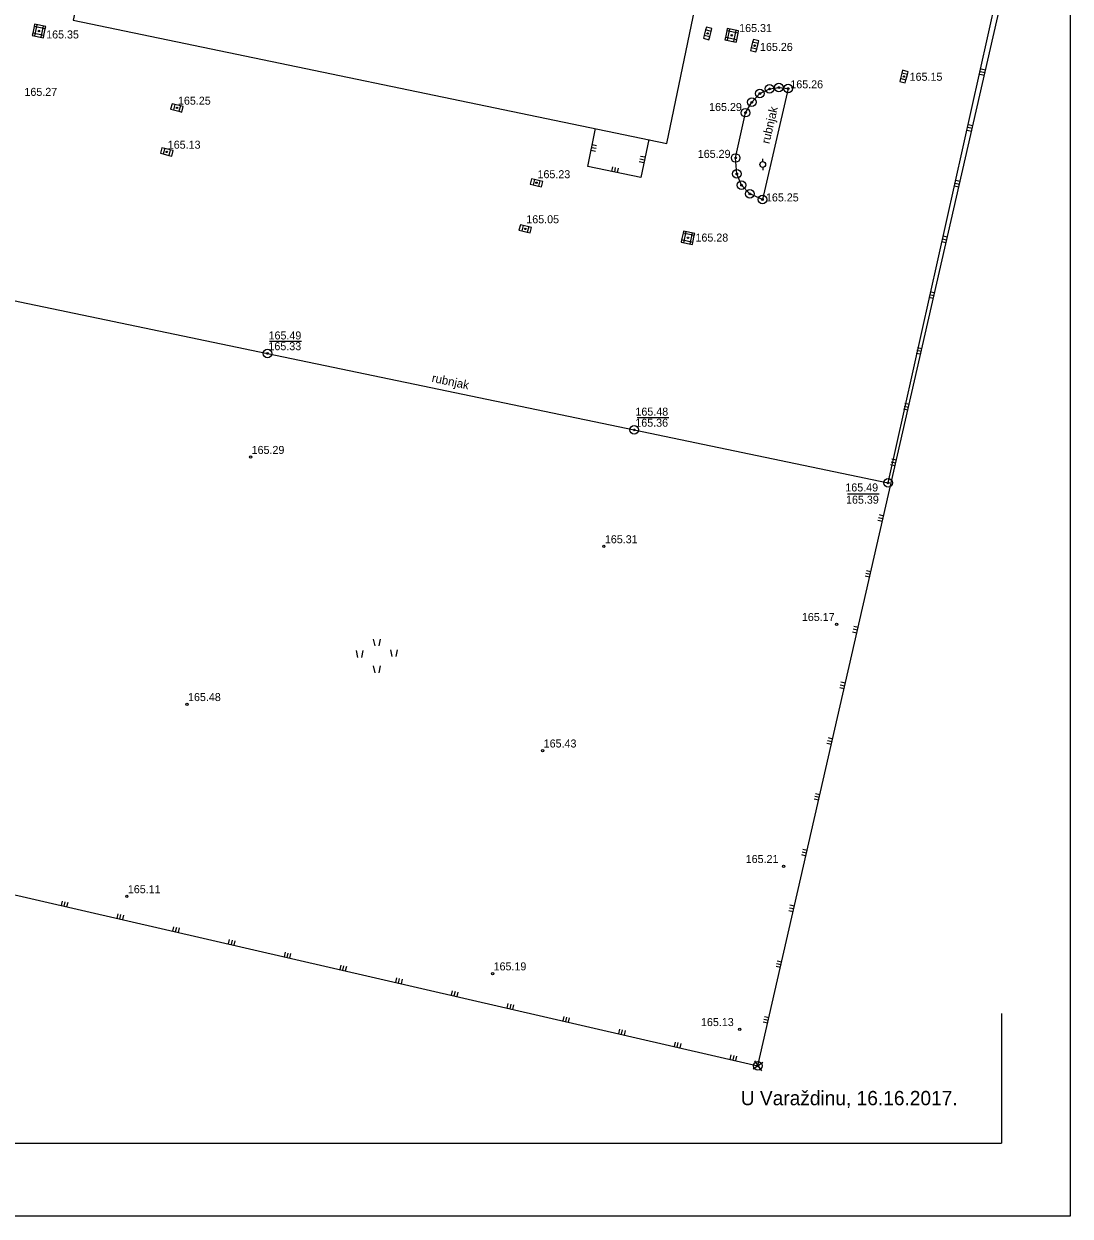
# Model space of a CAD drawing. Extents: x 492698 to 492905, y 5129124 to 5129334.
# Drawn here: x 492805.9 to 492897.4, y 5129123.7 to 5129228 of the extents above; entities that cross this region are included whole.
import ezdxf

# ---------------------------------------------------------------- set-up
doc = ezdxf.new("R2010")
doc.units = 0
for name, color, linetype in [('KUĆNI BROJ', 7, 'Continuous'), ('MEĐA - stara', 7, 'Continuous'), ('MEĐAŠI', 7, 'Continuous'), ('OBJEKTI - novi', 7, 'Continuous'), ('OBJEKTI - stari', 7, 'Continuous'), ('OBRAZCI', 7, 'Continuous'), ('TOPO - Znakovi', 7, 'Continuous'), ('VISINE', 7, 'Continuous')]:
    doc.layers.add(name, color=color, linetype=linetype)

msp = doc.modelspace()

# ---------------------------------------------------------------- linework, layer by layer
at = {"layer": 'MEĐA - stara'}
for p, q in [((492870.12, 5129136.86), (492891.58, 5129230.79)), ((492881.5, 5129187.83), (492890.99, 5129230.4)), ((492870.29, 5129221.87), (492871.14, 5129222.28)), ((492872.77, 5129222.31), (492870.51, 5129212.6)), ((492871.14, 5129222.28), (492871.94, 5129222.4)), ((492871.94, 5129222.4), (492872.77, 5129222.31)), ((492869.58, 5129221.11), (492870.29, 5129221.87)), ((492868.17, 5129216.24), (492869.04, 5129220.2)), ((492869.04, 5129220.2), (492869.58, 5129221.11)), ((492868.27, 5129214.85), (492868.17, 5129216.24)), ((492868.69, 5129213.86), (492868.27, 5129214.85)), ((492869.42, 5129213.1), (492868.69, 5129213.86)), ((492870.51, 5129212.6), (492869.42, 5129213.1)), ((492792.93, 5129206.3), (492827.24, 5129199.15)), ((492827.24, 5129199.15), (492859.31, 5129192.46)), ((492859.31, 5129192.46), (492881.5, 5129187.83)), ((492834.99, 5129173.17), (492835.12, 5129172.57)), ((492835.59, 5129173.17), (492835.47, 5129172.57)), ((492836.49, 5129174.17), (492836.62, 5129173.57)), ((492837.09, 5129174.17), (492836.97, 5129173.57)), ((492837.99, 5129173.24), (492838.12, 5129172.64)), ((492838.59, 5129173.24), (492838.47, 5129172.64)), ((492836.49, 5129171.82), (492836.62, 5129171.22)), ((492837.09, 5129171.82), (492836.97, 5129171.22)), ((492788.55, 5129155.62), (492870.12, 5129136.86))]:
    msp.add_line(p, q, dxfattribs=at)
at = {"layer": 'MEĐAŠI'}
for p, q in [((492870.55, 5129137.16), (492869.69, 5129136.56)), ((492869.82, 5129137.29), (492870.42, 5129136.43))]:
    msp.add_line(p, q, dxfattribs=at)
for centre, radius in [((492870.29, 5129221.87), 0.375), ((492871.14, 5129222.28), 0.375), ((492871.14, 5129222.28), 0.075), ((492871.94, 5129222.4), 0.375), ((492871.94, 5129222.4), 0.075), ((492872.77, 5129222.31), 0.375), ((492872.77, 5129222.31), 0.075), ((492869.58, 5129221.11), 0.375), ((492869.58, 5129221.11), 0.075), ((492870.29, 5129221.87), 0.075), ((492869.04, 5129220.2), 0.375), ((492869.04, 5129220.2), 0.075), ((492868.17, 5129216.24), 0.375), ((492868.17, 5129216.24), 0.075), ((492868.27, 5129214.85), 0.375), ((492868.27, 5129214.85), 0.075), ((492868.69, 5129213.86), 0.375), ((492868.69, 5129213.86), 0.075), ((492869.42, 5129213.1), 0.375), ((492869.42, 5129213.1), 0.075), ((492870.51, 5129212.6), 0.375), ((492870.51, 5129212.6), 0.075), ((492827.24, 5129199.15), 0.375), ((492827.24, 5129199.15), 0.075), ((492859.31, 5129192.46), 0.375), ((492859.31, 5129192.46), 0.075), ((492881.5, 5129187.83), 0.375), ((492881.5, 5129187.83), 0.075), ((492870.12, 5129136.86), 0.075)]:
    msp.add_circle(centre, radius, dxfattribs=at)
for start, end in [(170.0551, 350.0551), (350.0551, 170.0551)]:
    msp.add_arc((492870.12, 5129136.86), 0.075, start, end, dxfattribs=at)
at = {"layer": 'OBJEKTI - novi'}
msp.add_circle((492870.12, 5129136.86), 0.375, dxfattribs=at)
at = {"layer": 'OBJEKTI - stari'}
for p, q in [((492855.25, 5129215.5), (492855.91, 5129218.81)), ((492860.57, 5129217.85), (492859.87, 5129214.53)), ((492859.87, 5129214.53), (492855.25, 5129215.5))]:
    msp.add_line(p, q, dxfattribs=at)
msp.add_lwpolyline([(492818.96, 5129270.18), (492815.01, 5129251.01), (492812.14, 5129237.15), (492810.27, 5129228.29), (492862.15, 5129217.52), (492870.87, 5129259.44)], close=True, dxfattribs=at)
at = {"layer": 'OBRAZCI'}
for p, q in [((492897.41, 5129333.71), (492897.41, 5129123.71)), ((492891.41, 5129141.43), (492891.41, 5129130.09)), ((492754.91, 5129130.09), (492891.41, 5129130.09)), ((492897.41, 5129123.71), (492748.91, 5129123.71))]:
    msp.add_line(p, q, dxfattribs=at)
at = {"layer": 'TOPO - Znakovi'}
for p, q in [((492806.84, 5129227.74), (492806.72, 5129227.15)), ((492806.88, 5129227.93), (492806.84, 5129227.74)), ((492807.82, 5129227.53), (492806.84, 5129227.74)), ((492807.08, 5129227.89), (492806.87, 5129226.91)), ((492807.86, 5129227.73), (492806.88, 5129227.93)), ((492807.46, 5129226.79), (492807.67, 5129227.77)), ((492807.7, 5129226.94), (492807.82, 5129227.53)), ((492807.82, 5129227.53), (492807.86, 5129227.73)), ((492865.55, 5129227.44), (492865.42, 5129226.95)), ((492865.62, 5129227.68), (492865.55, 5129227.44)), ((492866.04, 5129227.31), (492865.55, 5129227.44)), ((492866.1, 5129227.55), (492865.62, 5129227.68)), ((492866.04, 5129227.31), (492866.1, 5129227.55)), ((492867.44, 5129227.56), (492867.4, 5129227.37)), ((492867.64, 5129227.52), (492867.43, 5129226.54)), ((492868.42, 5129227.36), (492867.44, 5129227.56)), ((492868.02, 5129226.42), (492868.23, 5129227.4)), ((492806.72, 5129227.15), (492806.68, 5129226.95)), ((492806.68, 5129226.95), (492807.66, 5129226.75)), ((492807.7, 5129226.94), (492806.72, 5129227.15)), ((492807.66, 5129226.75), (492807.7, 5129226.94)), ((492865.42, 5129226.95), (492865.36, 5129226.71)), ((492865.36, 5129226.71), (492865.84, 5129226.58)), ((492865.91, 5129226.82), (492865.42, 5129226.95)), ((492865.84, 5129226.58), (492865.91, 5129226.82)), ((492865.91, 5129226.82), (492866.04, 5129227.31)), ((492867.28, 5129226.78), (492867.24, 5129226.58)), ((492867.24, 5129226.58), (492868.22, 5129226.38)), ((492867.4, 5129227.37), (492867.28, 5129226.78)), ((492868.26, 5129226.57), (492867.28, 5129226.78)), ((492868.38, 5129227.16), (492867.4, 5129227.37)), ((492868.22, 5129226.38), (492868.26, 5129226.57)), ((492868.26, 5129226.57), (492868.38, 5129227.16)), ((492868.38, 5129227.16), (492868.42, 5129227.36)), ((492869.65, 5129226.37), (492869.52, 5129225.88)), ((492869.72, 5129226.61), (492869.65, 5129226.37)), ((492870.14, 5129226.24), (492869.65, 5129226.37)), ((492870.2, 5129226.48), (492869.72, 5129226.61)), ((492870.14, 5129226.24), (492870.2, 5129226.48)), ((492869.52, 5129225.88), (492869.46, 5129225.64)), ((492869.46, 5129225.64), (492869.94, 5129225.51)), ((492870.01, 5129225.75), (492869.52, 5129225.88)), ((492869.94, 5129225.51), (492870.01, 5129225.75)), ((492870.01, 5129225.75), (492870.14, 5129226.24)), ((492882.7, 5129223.67), (492882.57, 5129223.18)), ((492882.77, 5129223.91), (492882.7, 5129223.67)), ((492883.19, 5129223.54), (492882.7, 5129223.67)), ((492883.25, 5129223.78), (492882.77, 5129223.91)), ((492883.06, 5129223.05), (492883.19, 5129223.54)), ((492883.19, 5129223.54), (492883.25, 5129223.78)), ((492889.52, 5129223.56), (492889.91, 5129223.47)), ((492889.57, 5129223.8), (492889.96, 5129223.71)), ((492889.63, 5129224.04), (492890.02, 5129223.96)), ((492882.57, 5129223.18), (492882.51, 5129222.94)), ((492882.51, 5129222.94), (492882.99, 5129222.81)), ((492883.06, 5129223.05), (492882.57, 5129223.18)), ((492882.99, 5129222.81), (492883.06, 5129223.05)), ((492818.9, 5129220.98), (492818.78, 5129220.5)), ((492818.78, 5129220.5), (492819.03, 5129220.44)), ((492819.15, 5129220.92), (492818.9, 5129220.98)), ((492819.15, 5129220.92), (492819.03, 5129220.44)), ((492819.03, 5129220.44), (492819.51, 5129220.32)), ((492819.63, 5129220.8), (492819.15, 5129220.92)), ((492819.63, 5129220.8), (492819.51, 5129220.32)), ((492819.51, 5129220.32), (492819.76, 5129220.26)), ((492819.88, 5129220.74), (492819.63, 5129220.8)), ((492819.76, 5129220.26), (492819.88, 5129220.74)), ((492888.51, 5129219.17), (492888.9, 5129219.08)), ((492888.4, 5129218.68), (492888.79, 5129218.59)), ((492888.46, 5129218.93), (492888.85, 5129218.84)), ((492818.01, 5129217.13), (492817.89, 5129216.65)), ((492818.26, 5129217.07), (492818.01, 5129217.13)), ((492818.26, 5129217.07), (492818.14, 5129216.59)), ((492818.74, 5129216.95), (492818.26, 5129217.07)), ((492818.74, 5129216.95), (492818.62, 5129216.47)), ((492818.99, 5129216.89), (492818.74, 5129216.95)), ((492855.97, 5129217.06), (492855.58, 5129217.14)), ((492856.02, 5129217.31), (492855.63, 5129217.39)), ((492817.89, 5129216.65), (492818.14, 5129216.59)), ((492818.14, 5129216.59), (492818.62, 5129216.47)), ((492818.62, 5129216.47), (492818.87, 5129216.41)), ((492818.87, 5129216.41), (492818.99, 5129216.89)), ((492855.92, 5129216.82), (492855.53, 5129216.9)), ((492859.75, 5129215.92), (492860.14, 5129215.84)), ((492859.8, 5129216.16), (492860.2, 5129216.08)), ((492859.86, 5129216.41), (492860.25, 5129216.33)), ((492870.54, 5129215.92), (492870.54, 5129216.17)), ((492857.4, 5129215.46), (492857.32, 5129215.07)), ((492857.65, 5129215.41), (492857.57, 5129215.01)), ((492857.89, 5129215.35), (492857.81, 5129214.96)), ((492870.54, 5129215.42), (492870.54, 5129215.17)), ((492850.33, 5129214.43), (492850.21, 5129213.95)), ((492850.21, 5129213.95), (492850.46, 5129213.89)), ((492850.58, 5129214.37), (492850.33, 5129214.43)), ((492850.58, 5129214.37), (492850.46, 5129213.89)), ((492850.46, 5129213.89), (492850.94, 5129213.77)), ((492851.06, 5129214.25), (492850.58, 5129214.37)), ((492851.06, 5129214.25), (492850.94, 5129213.77)), ((492851.31, 5129214.19), (492851.06, 5129214.25)), ((492851.19, 5129213.71), (492851.31, 5129214.19)), ((492887.35, 5129214.05), (492887.74, 5129213.96)), ((492887.4, 5129214.3), (492887.79, 5129214.21)), ((492850.94, 5129213.77), (492851.19, 5129213.71)), ((492887.29, 5129213.81), (492887.68, 5129213.72)), ((492849.35, 5129210.4), (492849.23, 5129209.92)), ((492849.23, 5129209.92), (492849.48, 5129209.86)), ((492849.6, 5129210.34), (492849.35, 5129210.4)), ((492849.6, 5129210.34), (492849.48, 5129209.86)), ((492849.48, 5129209.86), (492849.96, 5129209.74)), ((492850.08, 5129210.22), (492849.6, 5129210.34)), ((492850.08, 5129210.22), (492849.96, 5129209.74)), ((492849.96, 5129209.74), (492850.21, 5129209.68)), ((492850.33, 5129210.16), (492850.08, 5129210.22)), ((492850.21, 5129209.68), (492850.33, 5129210.16)), ((492863.57, 5129209.66), (492863.45, 5129209.07)), ((492863.61, 5129209.85), (492863.57, 5129209.66)), ((492864.55, 5129209.45), (492863.57, 5129209.66)), ((492863.81, 5129209.81), (492863.6, 5129208.83)), ((492864.59, 5129209.65), (492863.61, 5129209.85)), ((492864.19, 5129208.71), (492864.4, 5129209.69)), ((492864.55, 5129209.45), (492864.59, 5129209.65)), ((492863.45, 5129209.07), (492863.41, 5129208.87)), ((492863.41, 5129208.87), (492864.39, 5129208.67)), ((492864.43, 5129208.86), (492863.45, 5129209.07)), ((492864.39, 5129208.67), (492864.43, 5129208.86)), ((492864.43, 5129208.86), (492864.55, 5129209.45)), ((492886.18, 5129208.93), (492886.57, 5129208.84)), ((492886.23, 5129209.18), (492886.62, 5129209.09)), ((492886.29, 5129209.42), (492886.68, 5129209.33)), ((492885.17, 5129204.55), (492885.56, 5129204.46)), ((492885.06, 5129204.06), (492885.45, 5129203.97)), ((492885.12, 5129204.3), (492885.51, 5129204.21)), ((492884, 5129199.43), (492884.39, 5129199.34)), ((492884.06, 5129199.67), (492884.45, 5129199.58)), ((492883.95, 5129199.18), (492884.34, 5129199.1)), ((492882.84, 5129194.31), (492883.23, 5129194.22)), ((492882.89, 5129194.55), (492883.28, 5129194.46)), ((492882.95, 5129194.8), (492883.34, 5129194.71)), ((492881.83, 5129189.92), (492882.22, 5129189.83)), ((492881.72, 5129189.44), (492882.11, 5129189.35)), ((492881.78, 5129189.68), (492882.17, 5129189.59)), ((492880.66, 5129184.81), (492881.05, 5129184.72)), ((492880.72, 5129185.05), (492881.11, 5129184.96)), ((492880.61, 5129184.56), (492881, 5129184.47)), ((492879.49, 5129179.69), (492879.88, 5129179.6)), ((492879.55, 5129179.93), (492879.94, 5129179.84)), ((492879.61, 5129180.17), (492880, 5129180.09)), ((492878.49, 5129175.3), (492878.88, 5129175.21)), ((492878.38, 5129174.81), (492878.77, 5129174.72)), ((492878.44, 5129175.06), (492878.83, 5129174.97)), ((492877.32, 5129170.18), (492877.71, 5129170.09)), ((492877.38, 5129170.43), (492877.77, 5129170.34)), ((492877.27, 5129169.94), (492877.66, 5129169.85)), ((492876.15, 5129165.06), (492876.54, 5129164.97)), ((492876.21, 5129165.31), (492876.6, 5129165.22)), ((492876.26, 5129165.55), (492876.65, 5129165.46)), ((492875.15, 5129160.68), (492875.54, 5129160.59)), ((492875.04, 5129160.19), (492875.43, 5129160.1)), ((492875.1, 5129160.43), (492875.49, 5129160.34)), ((492873.98, 5129155.56), (492874.37, 5129155.47)), ((492874.04, 5129155.8), (492874.43, 5129155.71)), ((492873.93, 5129155.32), (492874.32, 5129155.23)), ((492809.29, 5129151.26), (492809.2, 5129150.87)), ((492809.53, 5129151.2), (492809.44, 5129150.81)), ((492809.78, 5129151.15), (492809.69, 5129150.76)), ((492872.81, 5129150.44), (492873.2, 5129150.35)), ((492872.87, 5129150.68), (492873.26, 5129150.6)), ((492872.92, 5129150.93), (492873.31, 5129150.84)), ((492814.16, 5129150.14), (492814.07, 5129149.75)), ((492814.41, 5129150.08), (492814.32, 5129149.69)), ((492814.65, 5129150.03), (492814.56, 5129149.64)), ((492819.04, 5129149.02), (492818.95, 5129148.63)), ((492819.28, 5129148.96), (492819.19, 5129148.57)), ((492819.52, 5129148.91), (492819.43, 5129148.52)), ((492823.91, 5129147.9), (492823.82, 5129147.51)), ((492824.15, 5129147.84), (492824.06, 5129147.45)), ((492824.4, 5129147.79), (492824.31, 5129147.4)), ((492828.78, 5129146.78), (492828.69, 5129146.39)), ((492829.02, 5129146.72), (492828.94, 5129146.33)), ((492829.27, 5129146.67), (492829.18, 5129146.28)), ((492871.81, 5129146.05), (492872.2, 5129145.96)), ((492833.65, 5129145.66), (492833.56, 5129145.27)), ((492833.9, 5129145.6), (492833.81, 5129145.21)), ((492834.14, 5129145.55), (492834.05, 5129145.16)), ((492871.7, 5129145.57), (492872.09, 5129145.48)), ((492871.75, 5129145.81), (492872.14, 5129145.72)), ((492838.53, 5129144.54), (492838.44, 5129144.15)), ((492838.77, 5129144.48), (492838.68, 5129144.09)), ((492839.01, 5129144.42), (492838.92, 5129144.03)), ((492843.4, 5129143.42), (492843.31, 5129143.03)), ((492843.64, 5129143.36), (492843.55, 5129142.97)), ((492843.89, 5129143.3), (492843.8, 5129142.91)), ((492848.27, 5129142.3), (492848.18, 5129141.91)), ((492848.52, 5129142.24), (492848.43, 5129141.85)), ((492848.76, 5129142.18), (492848.67, 5129141.79)), ((492853.15, 5129141.17), (492853.06, 5129140.78)), ((492853.39, 5129141.12), (492853.3, 5129140.73)), ((492853.63, 5129141.06), (492853.54, 5129140.67)), ((492870.64, 5129140.94), (492871.03, 5129140.85)), ((492870.7, 5129141.18), (492871.09, 5129141.09)), ((492858.02, 5129140.05), (492857.93, 5129139.66)), ((492858.26, 5129140), (492858.17, 5129139.61)), ((492858.51, 5129139.94), (492858.42, 5129139.55)), ((492870.59, 5129140.69), (492870.98, 5129140.6)), ((492862.89, 5129138.93), (492862.8, 5129138.54)), ((492863.13, 5129138.88), (492863.04, 5129138.49)), ((492863.38, 5129138.82), (492863.29, 5129138.43)), ((492867.76, 5129137.81), (492867.67, 5129137.42)), ((492868.01, 5129137.76), (492867.92, 5129137.37)), ((492868.25, 5129137.7), (492868.16, 5129137.31))]:
    msp.add_line(p, q, dxfattribs=at)
for centre, radius in [((492807.27, 5129227.34), 0.065), ((492865.73, 5129227.13), 0.065), ((492867.83, 5129226.97), 0.065), ((492869.83, 5129226.06), 0.065), ((492882.88, 5129223.36), 0.065), ((492819.33, 5129220.62), 0.065), ((492818.44, 5129216.77), 0.065), ((492870.54, 5129215.67), 0.25), ((492850.76, 5129214.07), 0.065), ((492849.78, 5129210.04), 0.065), ((492864, 5129209.26), 0.065)]:
    msp.add_circle(centre, radius, dxfattribs=at)
at = {"layer": 'VISINE'}
for p, q in [((492827.43, 5129200.23), (492830.21, 5129200.23)), ((492859.55, 5129193.55), (492862.32, 5129193.55)), ((492877.96, 5129186.87), (492880.73, 5129186.87))]:
    msp.add_line(p, q, dxfattribs=at)
for centre in [(492825.77, 5129190.08), (492856.65, 5129182.27), (492876.99, 5129175.47), (492820.21, 5129168.47), (492851.3, 5129164.41), (492872.36, 5129154.31), (492814.95, 5129151.67), (492846.92, 5129144.92), (492868.53, 5129140.05)]:
    msp.add_circle(centre, 0.1, dxfattribs=at)

# ---------------------------------------------------------------- texts
at = {"layer": 'KUĆNI BROJ'}
for rotation, p in [(76.8977, (492871.12, 5129217.43)), (348.2167, (492841.56, 5129196.67))]:
    msp.add_text('rubnjak', height=0.75, rotation=rotation, dxfattribs=at).set_placement(p)
at = {"layer": 'OBRAZCI'}
msp.add_text('U Varaždinu, 16.16.2017.', height=1.25, dxfattribs=at).set_placement((492868.62, 5129133.41))
at = {"layer": 'VISINE'}
for s, p in [('165.35', (492807.9, 5129226.69)), ('165.31', (492868.48, 5129227.25)), ('165.26', (492870.3, 5129225.6)), ('165.15', (492883.38, 5129222.99)), ('165.27', (492806, 5129221.67)), ('165.26', (492872.95, 5129222.33)), ('165.25', (492819.42, 5129220.9)), ('165.29', (492865.85, 5129220.35)), ('165.13', (492818.53, 5129217.05)), ('165.29', (492864.86, 5129216.25)), ('165.23', (492850.85, 5129214.47)), ('165.25', (492870.82, 5129212.44)), ('165.05', (492849.87, 5129210.53)), ('165.28', (492864.66, 5129208.93)), ('165.49', (492827.34, 5129200.37)), ('165.33', (492827.33, 5129199.43)), ('165.48', (492859.41, 5129193.71)), ('165.36', (492859.4, 5129192.74)), ('165.29', (492825.86, 5129190.36)), ('165.49', (492877.76, 5129187.08)), ('165.39', (492877.82, 5129186.01)), ('165.31', (492856.74, 5129182.55)), ('165.17', (492873.96, 5129175.75)), ('165.48', (492820.3, 5129168.75)), ('165.43', (492851.39, 5129164.69)), ('165.21', (492869.05, 5129154.59)), ('165.11', (492815.04, 5129151.95)), ('165.19', (492847.01, 5129145.2)), ('165.13', (492865.14, 5129140.33))]:
    msp.add_text(s, height=0.7, dxfattribs=at).set_placement(p)

doc.saveas('drawing.dxf')
